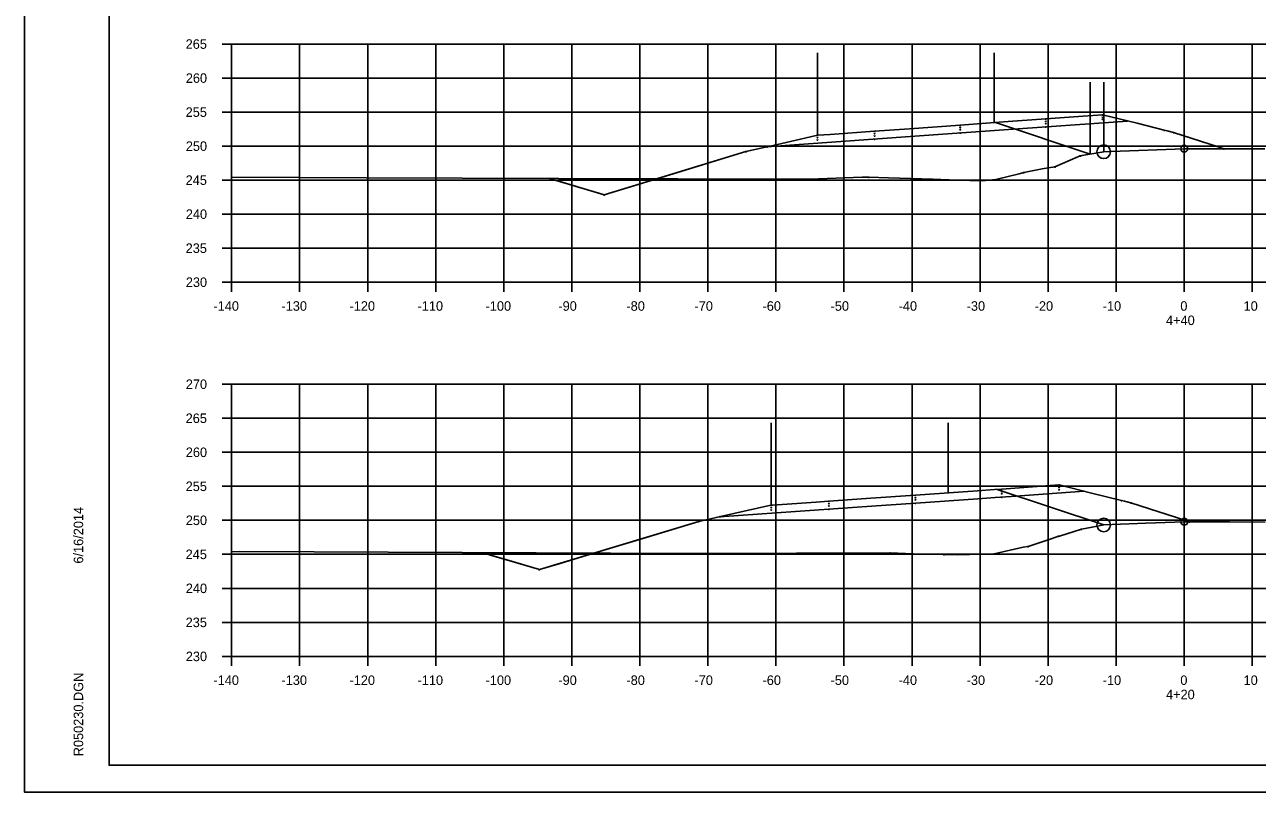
# Model space of a CAD drawing. Extents: x 1300404 to 1323571, y 234004 to 252077.
# Drawn here: x 1315546.9 to 1315728, y 241488.4 to 241601.3 of the extents above; entities that cross this region are included whole.
import ezdxf

# ---------------------------------------------------------------- set-up
doc = ezdxf.new("R2010")
doc.units = 0
for name, color, linetype in [('Default', 7, 'Continuous'), ('R_Axis', 7, 'Continuous'), ('R_Axis Annot', 7, 'Continuous'), ('R_Border', 7, 'Continuous'), ('R_Draft', 7, 'Continuous'), ('R_Exist Surface', 7, 'Continuous'), ('R_Fin Surface', 7, 'Continuous'), ('R_Grid', 7, 'Continuous'), ('R_MOT', 7, 'Continuous'), ('R_No Plot', 7, 'Continuous')]:
    doc.layers.add(name, color=color, linetype=linetype)

msp = doc.modelspace()

# ---------------------------------------------------------------- linework, layer by layer
at = {"layer": 'Default'}
for p, q in [((1315559.28, 241492.43), (1315559.28, 241697.89)), ((1315875.46, 241492.43), (1315559.28, 241492.43))]:
    msp.add_line(p, q, dxfattribs=at)
at = {"layer": 'R_Axis'}
for p, q in [((1315575.88, 241598.43), (1315577.28, 241598.43)), ((1315577.28, 241563.43), (1315577.28, 241598.43)), ((1315575.88, 241593.43), (1315577.28, 241593.43)), ((1315575.88, 241588.43), (1315577.28, 241588.43)), ((1315575.88, 241583.43), (1315577.28, 241583.43)), ((1315575.88, 241578.43), (1315577.28, 241578.43)), ((1315575.88, 241573.43), (1315577.28, 241573.43)), ((1315575.88, 241568.43), (1315577.28, 241568.43)), ((1315575.88, 241563.43), (1315577.28, 241563.43)), ((1315577.28, 241563.43), (1315857.28, 241563.43)), ((1315577.28, 241562.03), (1315577.28, 241563.43)), ((1315587.28, 241562.03), (1315587.28, 241563.43)), ((1315597.28, 241562.03), (1315597.28, 241563.43)), ((1315607.28, 241562.03), (1315607.28, 241563.43)), ((1315617.28, 241562.03), (1315617.28, 241563.43)), ((1315627.28, 241562.03), (1315627.28, 241563.43)), ((1315637.28, 241562.03), (1315637.28, 241563.43)), ((1315647.28, 241562.03), (1315647.28, 241563.43)), ((1315657.28, 241562.03), (1315657.28, 241563.43)), ((1315667.28, 241562.03), (1315667.28, 241563.43)), ((1315677.28, 241562.03), (1315677.28, 241563.43)), ((1315687.28, 241562.03), (1315687.28, 241563.43)), ((1315697.28, 241562.03), (1315697.28, 241563.43)), ((1315707.28, 241562.03), (1315707.28, 241563.43)), ((1315717.28, 241562.03), (1315717.28, 241563.43)), ((1315727.28, 241562.03), (1315727.28, 241563.43)), ((1315575.88, 241548.43), (1315577.28, 241548.43)), ((1315577.28, 241508.43), (1315577.28, 241548.43)), ((1315575.88, 241543.43), (1315577.28, 241543.43)), ((1315575.88, 241538.43), (1315577.28, 241538.43)), ((1315575.88, 241533.43), (1315577.28, 241533.43)), ((1315575.88, 241528.43), (1315577.28, 241528.43)), ((1315575.88, 241523.43), (1315577.28, 241523.43)), ((1315575.88, 241518.43), (1315577.28, 241518.43)), ((1315575.88, 241513.43), (1315577.28, 241513.43)), ((1315575.88, 241508.43), (1315577.28, 241508.43)), ((1315577.28, 241508.43), (1315857.28, 241508.43)), ((1315577.28, 241507.03), (1315577.28, 241508.43)), ((1315587.28, 241507.03), (1315587.28, 241508.43)), ((1315597.28, 241507.03), (1315597.28, 241508.43)), ((1315607.28, 241507.03), (1315607.28, 241508.43)), ((1315617.28, 241507.03), (1315617.28, 241508.43)), ((1315627.28, 241507.03), (1315627.28, 241508.43)), ((1315637.28, 241507.03), (1315637.28, 241508.43)), ((1315647.28, 241507.03), (1315647.28, 241508.43)), ((1315657.28, 241507.03), (1315657.28, 241508.43)), ((1315667.28, 241507.03), (1315667.28, 241508.43)), ((1315677.28, 241507.03), (1315677.28, 241508.43)), ((1315687.28, 241507.03), (1315687.28, 241508.43)), ((1315697.28, 241507.03), (1315697.28, 241508.43)), ((1315707.28, 241507.03), (1315707.28, 241508.43)), ((1315717.28, 241507.03), (1315717.28, 241508.43)), ((1315727.28, 241507.03), (1315727.28, 241508.43))]:
    msp.add_line(p, q, dxfattribs=at)
at = {"layer": 'R_Border'}
msp.add_line((1315559.28, 241492.43), (1315559.28, 241492.43), dxfattribs=at)
at = {"layer": 'R_Draft'}
for points in [[(1315705.28, 241588.08), (1315705.33, 241587.98), (1315705.23, 241587.98)], [(1315705.28, 241587.75), (1315705.33, 241587.65), (1315705.23, 241587.65)], [(1315684.36, 241586.57), (1315684.41, 241586.47), (1315684.31, 241586.47)], [(1315684.36, 241586.24), (1315684.41, 241586.14), (1315684.31, 241586.14)], [(1315684.36, 241585.91), (1315684.41, 241585.81), (1315684.31, 241585.81)], [(1315696.93, 241587.48), (1315696.98, 241587.38), (1315696.88, 241587.38)], [(1315696.93, 241587.14), (1315696.98, 241587.04), (1315696.88, 241587.04)], [(1315696.93, 241586.81), (1315696.98, 241586.71), (1315696.88, 241586.71)], [(1315696.93, 241586.31), (1315696.98, 241586.21), (1315696.88, 241586.21)], [(1315705.28, 241587.42), (1315705.33, 241587.32), (1315705.23, 241587.32)], [(1315663.37, 241585.08), (1315663.42, 241584.98), (1315663.32, 241584.98)], [(1315663.37, 241584.75), (1315663.42, 241584.65), (1315663.32, 241584.65)], [(1315663.37, 241584.42), (1315663.42, 241584.32), (1315663.32, 241584.32)], [(1315671.77, 241585.67), (1315671.82, 241585.57), (1315671.72, 241585.57)], [(1315671.77, 241585.34), (1315671.82, 241585.24), (1315671.72, 241585.24)], [(1315671.77, 241585.01), (1315671.82, 241584.91), (1315671.72, 241584.91)], [(1315671.77, 241584.51), (1315671.82, 241584.41), (1315671.72, 241584.41)], [(1315684.36, 241585.41), (1315684.41, 241585.31), (1315684.31, 241585.31)], [(1315714.36, 241585.84), (1315714.41, 241585.74), (1315714.31, 241585.74)], [(1315715.73, 241585.5), (1315715.78, 241585.4), (1315715.68, 241585.4)], [(1315652.86, 241582.68), (1315652.91, 241582.58), (1315652.81, 241582.58)], [(1315655.99, 241583.39), (1315656.04, 241583.29), (1315655.94, 241583.29)], [(1315723.11, 241583.09), (1315723.16, 241582.99), (1315723.06, 241582.99)], [(1315723.11, 241583.09), (1315723.16, 241582.99), (1315723.06, 241582.99)], [(1315701.99, 241582.05), (1315702.04, 241581.95), (1315701.94, 241581.95)], [(1315624.06, 241578.73), (1315624.11, 241578.63), (1315624.01, 241578.63)], [(1315624.06, 241578.73), (1315624.11, 241578.63), (1315624.01, 241578.63)], [(1315639.44, 241578.67), (1315639.49, 241578.57), (1315639.39, 241578.57)], [(1315670.92, 241578.93), (1315670.97, 241578.83), (1315670.87, 241578.83)], [(1315693.71, 241579.6), (1315693.76, 241579.5), (1315693.66, 241579.5)], [(1315698.29, 241580.43), (1315698.34, 241580.33), (1315698.24, 241580.33)], [(1315662.26, 241578.63), (1315662.31, 241578.53), (1315662.21, 241578.53)], [(1315680.3, 241578.62), (1315680.35, 241578.52), (1315680.25, 241578.52)], [(1315689.61, 241578.58), (1315689.66, 241578.48), (1315689.56, 241578.48)], [(1315632.06, 241576.3), (1315632.11, 241576.2), (1315632.01, 241576.2)], [(1315698.89, 241533.67), (1315698.94, 241533.57), (1315698.84, 241533.57)], [(1315677.77, 241532.18), (1315677.82, 241532.08), (1315677.72, 241532.08)], [(1315677.77, 241531.85), (1315677.82, 241531.75), (1315677.72, 241531.75)], [(1315690.46, 241533.07), (1315690.51, 241532.97), (1315690.41, 241532.97)], [(1315690.46, 241532.74), (1315690.51, 241532.64), (1315690.41, 241532.64)], [(1315690.46, 241532.41), (1315690.51, 241532.31), (1315690.41, 241532.31)], [(1315690.46, 241531.9), (1315690.51, 241531.8), (1315690.41, 241531.8)], [(1315698.89, 241533.33), (1315698.94, 241533.23), (1315698.84, 241533.23)], [(1315698.89, 241533), (1315698.94, 241532.9), (1315698.84, 241532.9)], [(1315656.59, 241530.71), (1315656.64, 241530.61), (1315656.54, 241530.61)], [(1315656.59, 241530.37), (1315656.64, 241530.27), (1315656.54, 241530.27)], [(1315656.59, 241530.04), (1315656.64, 241529.94), (1315656.54, 241529.94)], [(1315665.06, 241531.3), (1315665.11, 241531.2), (1315665.01, 241531.2)], [(1315665.06, 241530.96), (1315665.11, 241530.86), (1315665.01, 241530.86)], [(1315665.06, 241530.63), (1315665.11, 241530.53), (1315665.01, 241530.53)], [(1315665.06, 241530.13), (1315665.11, 241530.03), (1315665.01, 241530.03)], [(1315677.77, 241531.52), (1315677.82, 241531.42), (1315677.72, 241531.42)], [(1315677.77, 241531.01), (1315677.82, 241530.91), (1315677.72, 241530.91)], [(1315708.06, 241531.41), (1315708.11, 241531.31), (1315708.01, 241531.31)], [(1315709.44, 241531.07), (1315709.49, 241530.97), (1315709.39, 241530.97)], [(1315645.94, 241528.31), (1315645.99, 241528.21), (1315645.89, 241528.21)], [(1315649.11, 241529.03), (1315649.16, 241528.93), (1315649.06, 241528.93)], [(1315718.08, 241528.27), (1315718.13, 241528.17), (1315718.03, 241528.17)], [(1315718.08, 241528.27), (1315718.13, 241528.17), (1315718.03, 241528.17)], [(1315698.8, 241526.13), (1315698.85, 241526.03), (1315698.75, 241526.03)], [(1315702.17, 241527.18), (1315702.22, 241527.08), (1315702.12, 241527.08)], [(1315694.37, 241524.64), (1315694.42, 241524.54), (1315694.32, 241524.54)], [(1315614.16, 241523.72), (1315614.21, 241523.62), (1315614.11, 241523.62)], [(1315614.16, 241523.72), (1315614.21, 241523.62), (1315614.11, 241523.62)], [(1315632.91, 241523.64), (1315632.96, 241523.54), (1315632.86, 241523.54)], [(1315661.62, 241523.64), (1315661.67, 241523.54), (1315661.57, 241523.54)], [(1315674.06, 241523.68), (1315674.11, 241523.58), (1315674.01, 241523.58)], [(1315681.97, 241523.44), (1315682.02, 241523.34), (1315681.92, 241523.34)], [(1315689.35, 241523.56), (1315689.4, 241523.46), (1315689.3, 241523.46)], [(1315622.51, 241521.23), (1315622.56, 241521.13), (1315622.46, 241521.13)]]:
    msp.add_lwpolyline(points, close=True, dxfattribs=at)
at = {"layer": 'R_Exist Surface'}
for points in [[(1315577.28, 241578.88), (1315597.05, 241578.79), (1315639.44, 241578.62), (1315639.78, 241578.62), (1315642.84, 241578.61), (1315660.96, 241578.59), (1315662.26, 241578.58), (1315669.95, 241578.85), (1315670.92, 241578.88), (1315673.81, 241578.78), (1315680.3, 241578.57), (1315683.97, 241578.42), (1315687.58, 241578.34), (1315689.61, 241578.53), (1315693.04, 241579.36), (1315693.71, 241579.55), (1315696.41, 241580.07), (1315698.29, 241580.38), (1315701.67, 241581.84), (1315701.99, 241582), (1315702.26, 241582.04), (1315705.45, 241582.6), (1315706.56, 241582.64), (1315717.28, 241583.05), (1315718.88, 241583.05), (1315729.11, 241583.02)], [(1315577.28, 241523.82), (1315578.43, 241523.83), (1315589.41, 241523.79), (1315632.91, 241523.59), (1315637.65, 241523.57), (1315660.29, 241523.61), (1315661.62, 241523.59), (1315662.33, 241523.6), (1315674.06, 241523.63), (1315677.43, 241523.52), (1315681.97, 241523.39), (1315683.91, 241523.38), (1315689.35, 241523.51), (1315693.62, 241524.48), (1315694.37, 241524.59), (1315697.73, 241525.72), (1315698.8, 241526.08), (1315698.97, 241526.12), (1315702.17, 241527.13), (1315703.73, 241527.44), (1315705.45, 241527.75), (1315711.66, 241528), (1315717.3, 241528.22), (1315723.92, 241528.2), (1315729.18, 241528.17)]]:
    msp.add_lwpolyline(points, dxfattribs=at)
at = {"layer": 'R_Fin Surface'}
for points in [[(1315624.06, 241578.68), (1315624.98, 241578.4), (1315628.25, 241577.41), (1315631.24, 241576.5), (1315632.06, 241576.25), (1315642.81, 241579.54), (1315652.86, 241582.63), (1315655.75, 241583.28), (1315655.99, 241583.34), (1315658.14, 241583.83), (1315662.37, 241584.8), (1315663.37, 241585.03), (1315665.26, 241585.16), (1315671.77, 241585.62), (1315676.92, 241585.99), (1315684.36, 241586.52), (1315690.71, 241586.98), (1315696.93, 241587.43), (1315702.43, 241587.82), (1315705.28, 241588.03), (1315710.37, 241586.78), (1315714.36, 241585.79), (1315714.79, 241585.68), (1315715.73, 241585.45), (1315722.25, 241583.32), (1315723.11, 241583.04)], [(1315614.16, 241523.67), (1315617.72, 241522.61), (1315622.51, 241521.18), (1315625.58, 241522.1), (1315628.92, 241523.11), (1315638.21, 241525.92), (1315645.94, 241528.26), (1315647.02, 241528.51), (1315649.11, 241528.98), (1315656.52, 241530.64), (1315656.59, 241530.66), (1315656.63, 241530.66), (1315656.76, 241530.67), (1315663.18, 241531.11), (1315665.06, 241531.25), (1315671.25, 241531.68), (1315677.77, 241532.13), (1315686.88, 241532.77), (1315689.42, 241532.95), (1315690.46, 241533.02), (1315691.75, 241533.11), (1315698.89, 241533.62), (1315703.67, 241532.44), (1315708.06, 241531.36), (1315708.51, 241531.25), (1315709.44, 241531.02), (1315717.52, 241528.4), (1315718.08, 241528.22)]]:
    msp.add_lwpolyline(points, dxfattribs=at)
at = {"layer": 'R_Grid'}
for p, q in [((1315577.28, 241598.43), (1315857.28, 241598.43)), ((1315577.28, 241563.43), (1315577.28, 241598.43)), ((1315587.28, 241563.43), (1315587.28, 241598.43)), ((1315597.28, 241563.43), (1315597.28, 241598.43)), ((1315607.28, 241563.43), (1315607.28, 241598.43)), ((1315617.28, 241563.43), (1315617.28, 241598.43)), ((1315627.28, 241563.43), (1315627.28, 241598.43)), ((1315637.28, 241563.43), (1315637.28, 241598.43)), ((1315647.28, 241563.43), (1315647.28, 241598.43)), ((1315657.28, 241563.43), (1315657.28, 241598.43)), ((1315667.28, 241563.43), (1315667.28, 241598.43)), ((1315677.28, 241563.43), (1315677.28, 241598.43)), ((1315687.28, 241563.43), (1315687.28, 241598.43)), ((1315697.28, 241563.43), (1315697.28, 241598.43)), ((1315707.28, 241563.43), (1315707.28, 241598.43)), ((1315717.28, 241563.43), (1315717.28, 241598.43)), ((1315727.28, 241563.43), (1315727.28, 241598.43)), ((1315577.28, 241593.43), (1315857.28, 241593.43)), ((1315577.28, 241588.43), (1315857.28, 241588.43)), ((1315577.28, 241583.43), (1315857.28, 241583.43)), ((1315577.28, 241578.43), (1315857.28, 241578.43)), ((1315577.28, 241573.43), (1315857.28, 241573.43)), ((1315577.28, 241568.43), (1315857.28, 241568.43)), ((1315577.28, 241563.43), (1315857.28, 241563.43)), ((1315577.28, 241548.43), (1315857.28, 241548.43)), ((1315577.28, 241508.43), (1315577.28, 241548.43)), ((1315587.28, 241508.43), (1315587.28, 241548.43)), ((1315597.28, 241508.43), (1315597.28, 241548.43)), ((1315607.28, 241508.43), (1315607.28, 241548.43)), ((1315617.28, 241508.43), (1315617.28, 241548.43)), ((1315627.28, 241508.43), (1315627.28, 241548.43)), ((1315637.28, 241508.43), (1315637.28, 241548.43)), ((1315647.28, 241508.43), (1315647.28, 241548.43)), ((1315657.28, 241508.43), (1315657.28, 241548.43)), ((1315667.28, 241508.43), (1315667.28, 241548.43)), ((1315677.28, 241508.43), (1315677.28, 241548.43)), ((1315687.28, 241508.43), (1315687.28, 241548.43)), ((1315697.28, 241508.43), (1315697.28, 241548.43)), ((1315707.28, 241508.43), (1315707.28, 241548.43)), ((1315717.28, 241508.43), (1315717.28, 241548.43)), ((1315727.28, 241508.43), (1315727.28, 241548.43)), ((1315577.28, 241543.43), (1315857.28, 241543.43)), ((1315577.28, 241538.43), (1315857.28, 241538.43)), ((1315577.28, 241533.43), (1315857.28, 241533.43)), ((1315577.28, 241528.43), (1315857.28, 241528.43)), ((1315577.28, 241523.43), (1315857.28, 241523.43)), ((1315577.28, 241518.43), (1315857.28, 241518.43)), ((1315577.28, 241513.43), (1315857.28, 241513.43)), ((1315577.28, 241508.43), (1315857.28, 241508.43))]:
    msp.add_line(p, q, dxfattribs=at)
at = {"layer": 'R_MOT'}
for p, q in [((1315663.37, 241585.03), (1315663.37, 241597.12)), ((1315689.37, 241586.84), (1315689.37, 241597.12)), ((1315703.45, 241582.25), (1315703.45, 241592.81)), ((1315705.45, 241582.6), (1315705.45, 241592.81)), ((1315689.53, 241586.89), (1315703.45, 241582.25)), ((1315656.59, 241530.66), (1315656.59, 241542.75)), ((1315682.59, 241532.47), (1315682.59, 241542.75)), ((1315689.78, 241532.97), (1315705.45, 241527.75))]:
    msp.add_line(p, q, dxfattribs=at)
for points in [[(1315655.96, 241583.33), (1315677, 241584.82), (1315690.79, 241585.81), (1315708.96, 241587.12)], [(1315649, 241528.95), (1315671.33, 241530.51), (1315677.85, 241530.96), (1315686.96, 241531.6), (1315689.5, 241531.78), (1315691.84, 241531.95), (1315702.6, 241532.71)]]:
    msp.add_lwpolyline(points, dxfattribs=at)
at = {"layer": 'R_No Plot'}
msp.add_line((1315546.87, 241488.45), (1315880.21, 241488.45), dxfattribs=at)
for points in [[(1315546.87, 241701.78), (1315880.21, 241701.78), (1315880.21, 241488.45), (1315546.87, 241488.45)], [(1315793.2, 241697.89), (1315793.2, 241688.01), (1315828.93, 241688.01), (1315828.93, 241685.09), (1315852.13, 241685.09), (1315852.13, 241662.97), (1315875.46, 241662.97), (1315875.46, 241492.43), (1315559.28, 241492.43), (1315559.28, 241697.89)]]:
    msp.add_lwpolyline(points, close=True, dxfattribs=at)
for points in [[(1315652.86, 241582.63), (1315632.06, 241576.25), (1315624.06, 241578.68)], [(1315652.86, 241582.63), (1315632.06, 241576.25), (1315624.06, 241578.68)], [(1315652.86, 241582.63), (1315632.06, 241576.25), (1315624.06, 241578.68)], [(1315652.86, 241582.63), (1315632.06, 241576.25), (1315624.06, 241578.68)], [(1315652.86, 241582.63), (1315632.06, 241576.25), (1315624.06, 241578.68)], [(1315632.06, 241576.25), (1315624.06, 241578.68)], [(1315645.94, 241528.26), (1315622.51, 241521.18), (1315614.16, 241523.67)], [(1315645.94, 241528.26), (1315622.51, 241521.18), (1315614.16, 241523.67)], [(1315645.94, 241528.26), (1315622.51, 241521.18), (1315614.16, 241523.67)], [(1315645.94, 241528.26), (1315622.51, 241521.18), (1315614.16, 241523.67)], [(1315645.94, 241528.26), (1315622.51, 241521.18), (1315614.16, 241523.67)], [(1315622.51, 241521.18), (1315614.16, 241523.67)]]:
    msp.add_lwpolyline(points, dxfattribs=at)
for centre, radius in [((1315705.45, 241582.6), 1), ((1315717.28, 241583.05), 0.5), ((1315705.45, 241527.75), 1), ((1315717.3, 241528.22), 0.5)]:
    msp.add_circle(centre, radius, dxfattribs=at)

# ---------------------------------------------------------------- texts
at = {"layer": 'R_Axis'}
for p in [(1315577.28, 241563.43), (1315577.28, 241508.43)]:
    msp.add_text('-', height=0.0001, dxfattribs=at).set_placement(p)
at = {"layer": 'R_Axis Annot'}
for s, p in [('265', (1315570.53, 241597.73)), ('260', (1315570.55, 241592.73)), ('255', (1315570.53, 241587.73)), ('250', (1315570.55, 241582.73)), ('245', (1315570.53, 241577.73)), ('240', (1315570.55, 241572.73)), ('235', (1315570.53, 241567.73)), ('230', (1315570.55, 241562.73)), ('-140', (1315574.61, 241559.23)), ('-130', (1315584.61, 241559.23)), ('-120', (1315594.61, 241559.23)), ('-110', (1315604.61, 241559.23)), ('-100', (1315614.61, 241559.23)), ('-90', (1315625.31, 241559.23)), ('-80', (1315635.31, 241559.23)), ('-70', (1315645.31, 241559.23)), ('-60', (1315655.31, 241559.23)), ('-50', (1315665.31, 241559.23)), ('-40', (1315675.31, 241559.23)), ('-30', (1315685.31, 241559.23)), ('-20', (1315695.31, 241559.23)), ('-10', (1315705.31, 241559.23)), ('0', (1315716.71, 241559.23)), ('10', (1315726.01, 241559.23)), ('4+40', (1315714.61, 241557.13)), ('270', (1315570.55, 241547.73)), ('265', (1315570.53, 241542.73)), ('260', (1315570.55, 241537.73)), ('255', (1315570.53, 241532.73)), ('250', (1315570.55, 241527.73)), ('245', (1315570.53, 241522.73)), ('240', (1315570.55, 241517.73)), ('235', (1315570.53, 241512.73)), ('230', (1315570.55, 241507.73)), ('-140', (1315574.61, 241504.23)), ('-130', (1315584.61, 241504.23)), ('-120', (1315594.61, 241504.23)), ('-110', (1315604.61, 241504.23)), ('-100', (1315614.61, 241504.23)), ('-90', (1315625.31, 241504.23)), ('-80', (1315635.31, 241504.23)), ('-70', (1315645.31, 241504.23)), ('-60', (1315655.31, 241504.23)), ('-50', (1315665.31, 241504.23)), ('-40', (1315675.31, 241504.23)), ('-30', (1315685.31, 241504.23)), ('-20', (1315695.31, 241504.23)), ('-10', (1315705.31, 241504.23)), ('0', (1315716.71, 241504.23)), ('10', (1315726.01, 241504.23)), ('4+20', (1315714.61, 241502.13))]:
    msp.add_text(s, height=1.4, dxfattribs=at).set_placement(p)
at = {"layer": 'R_Border'}
for s, p in [('6/16/2014', (1315555.47, 241522.07)), ('R050230.DGN', (1315555.47, 241493.75))]:
    msp.add_text(s, height=1.4, rotation=90, dxfattribs=at).set_placement(p)

doc.saveas('drawing.dxf')
